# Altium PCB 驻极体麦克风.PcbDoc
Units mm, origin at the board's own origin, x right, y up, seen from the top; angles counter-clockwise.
Board outline 39.6 x 39.6 mm, 2 copper layers (Top Layer, Bottom Layer); 11 components, 10 nets, 34 pads, 3 vias.
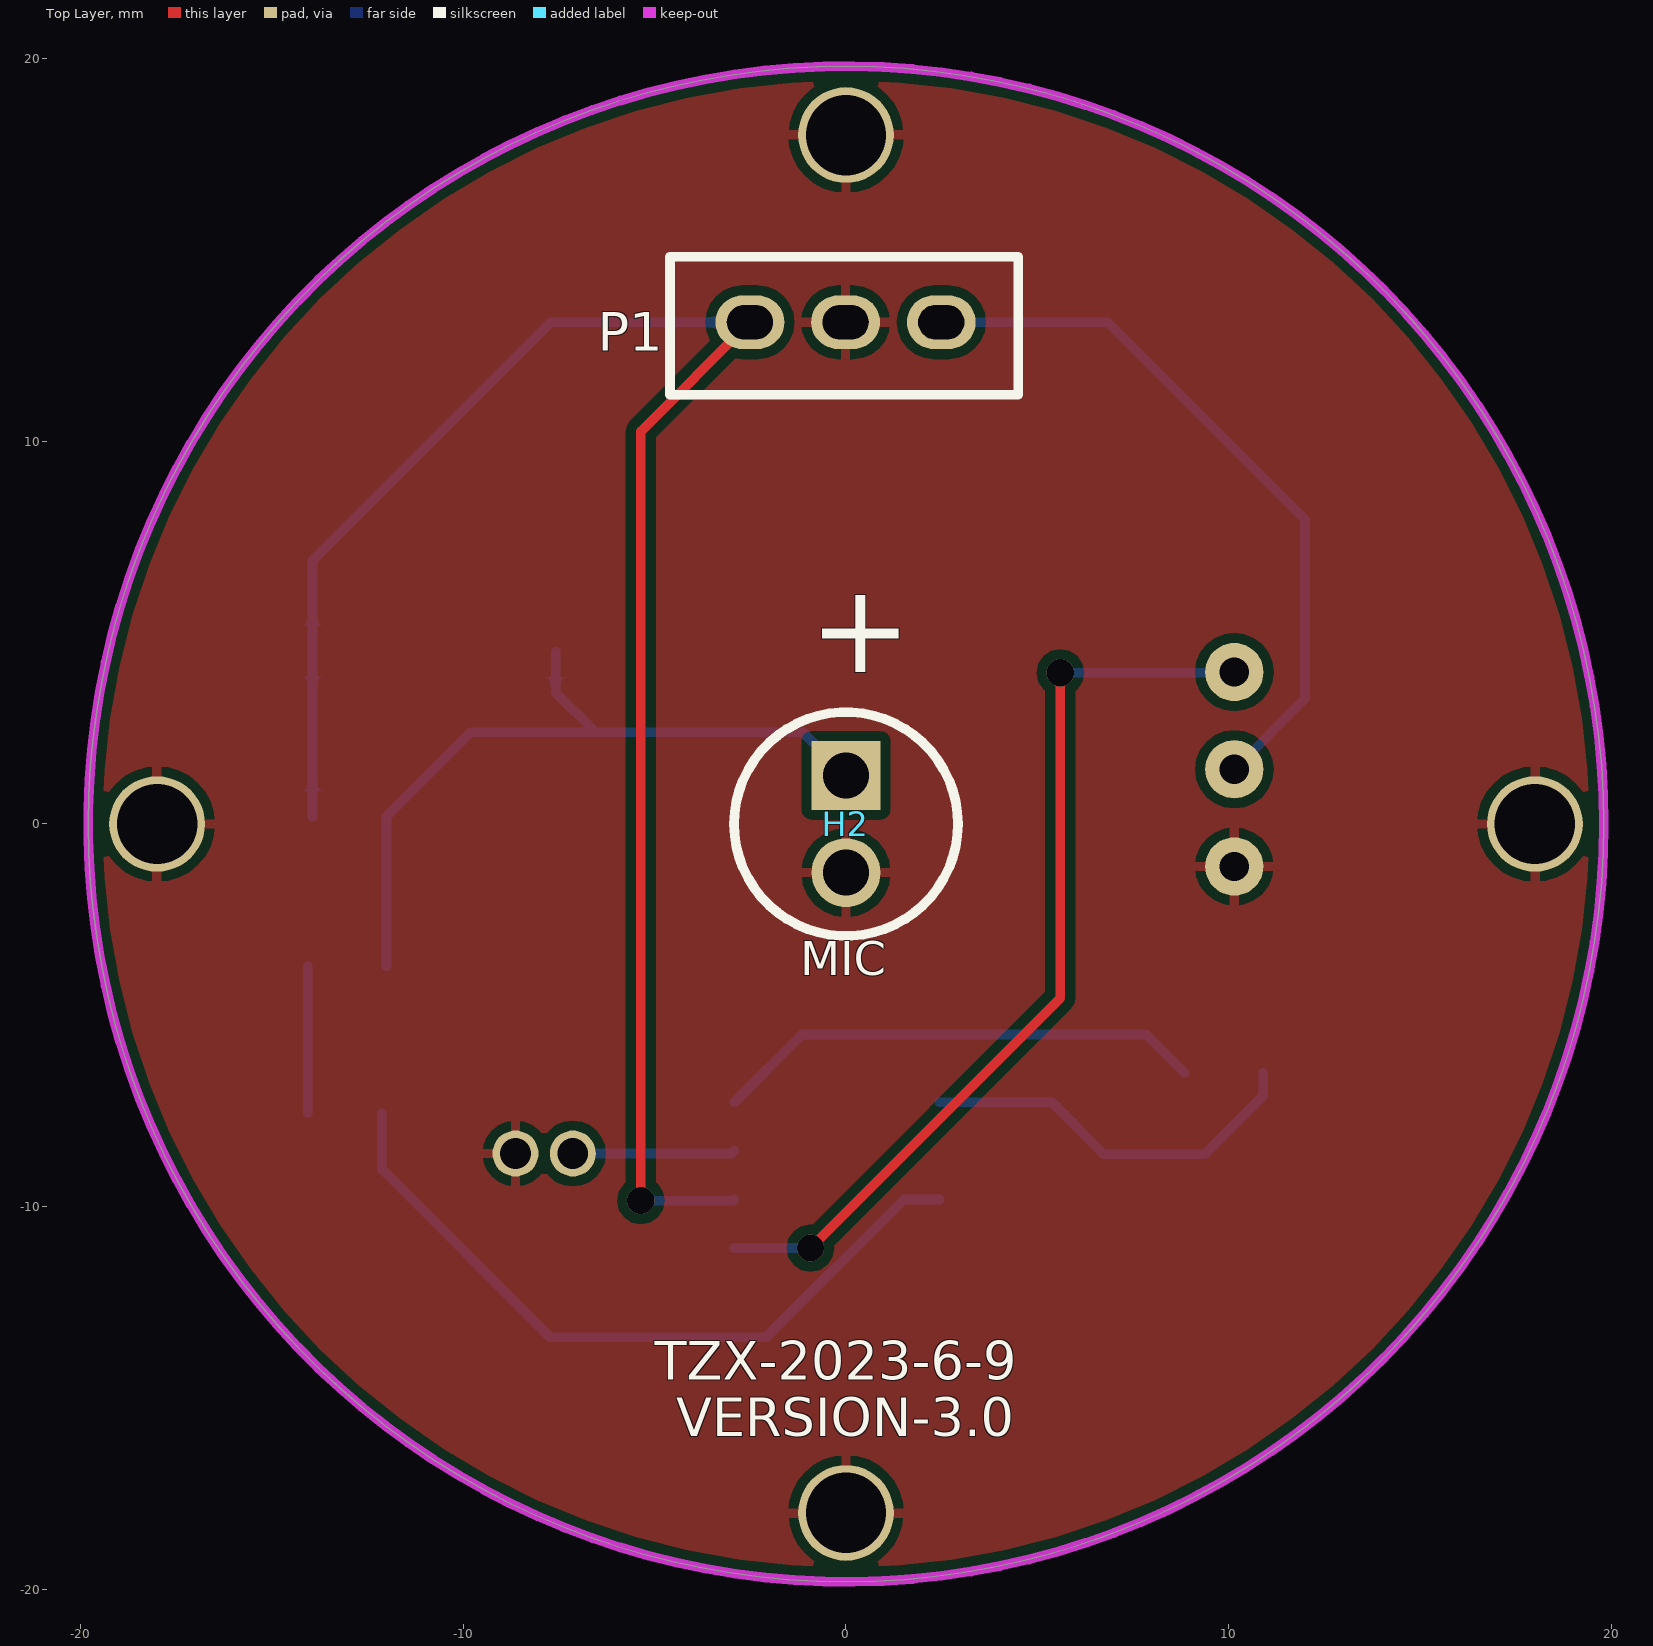
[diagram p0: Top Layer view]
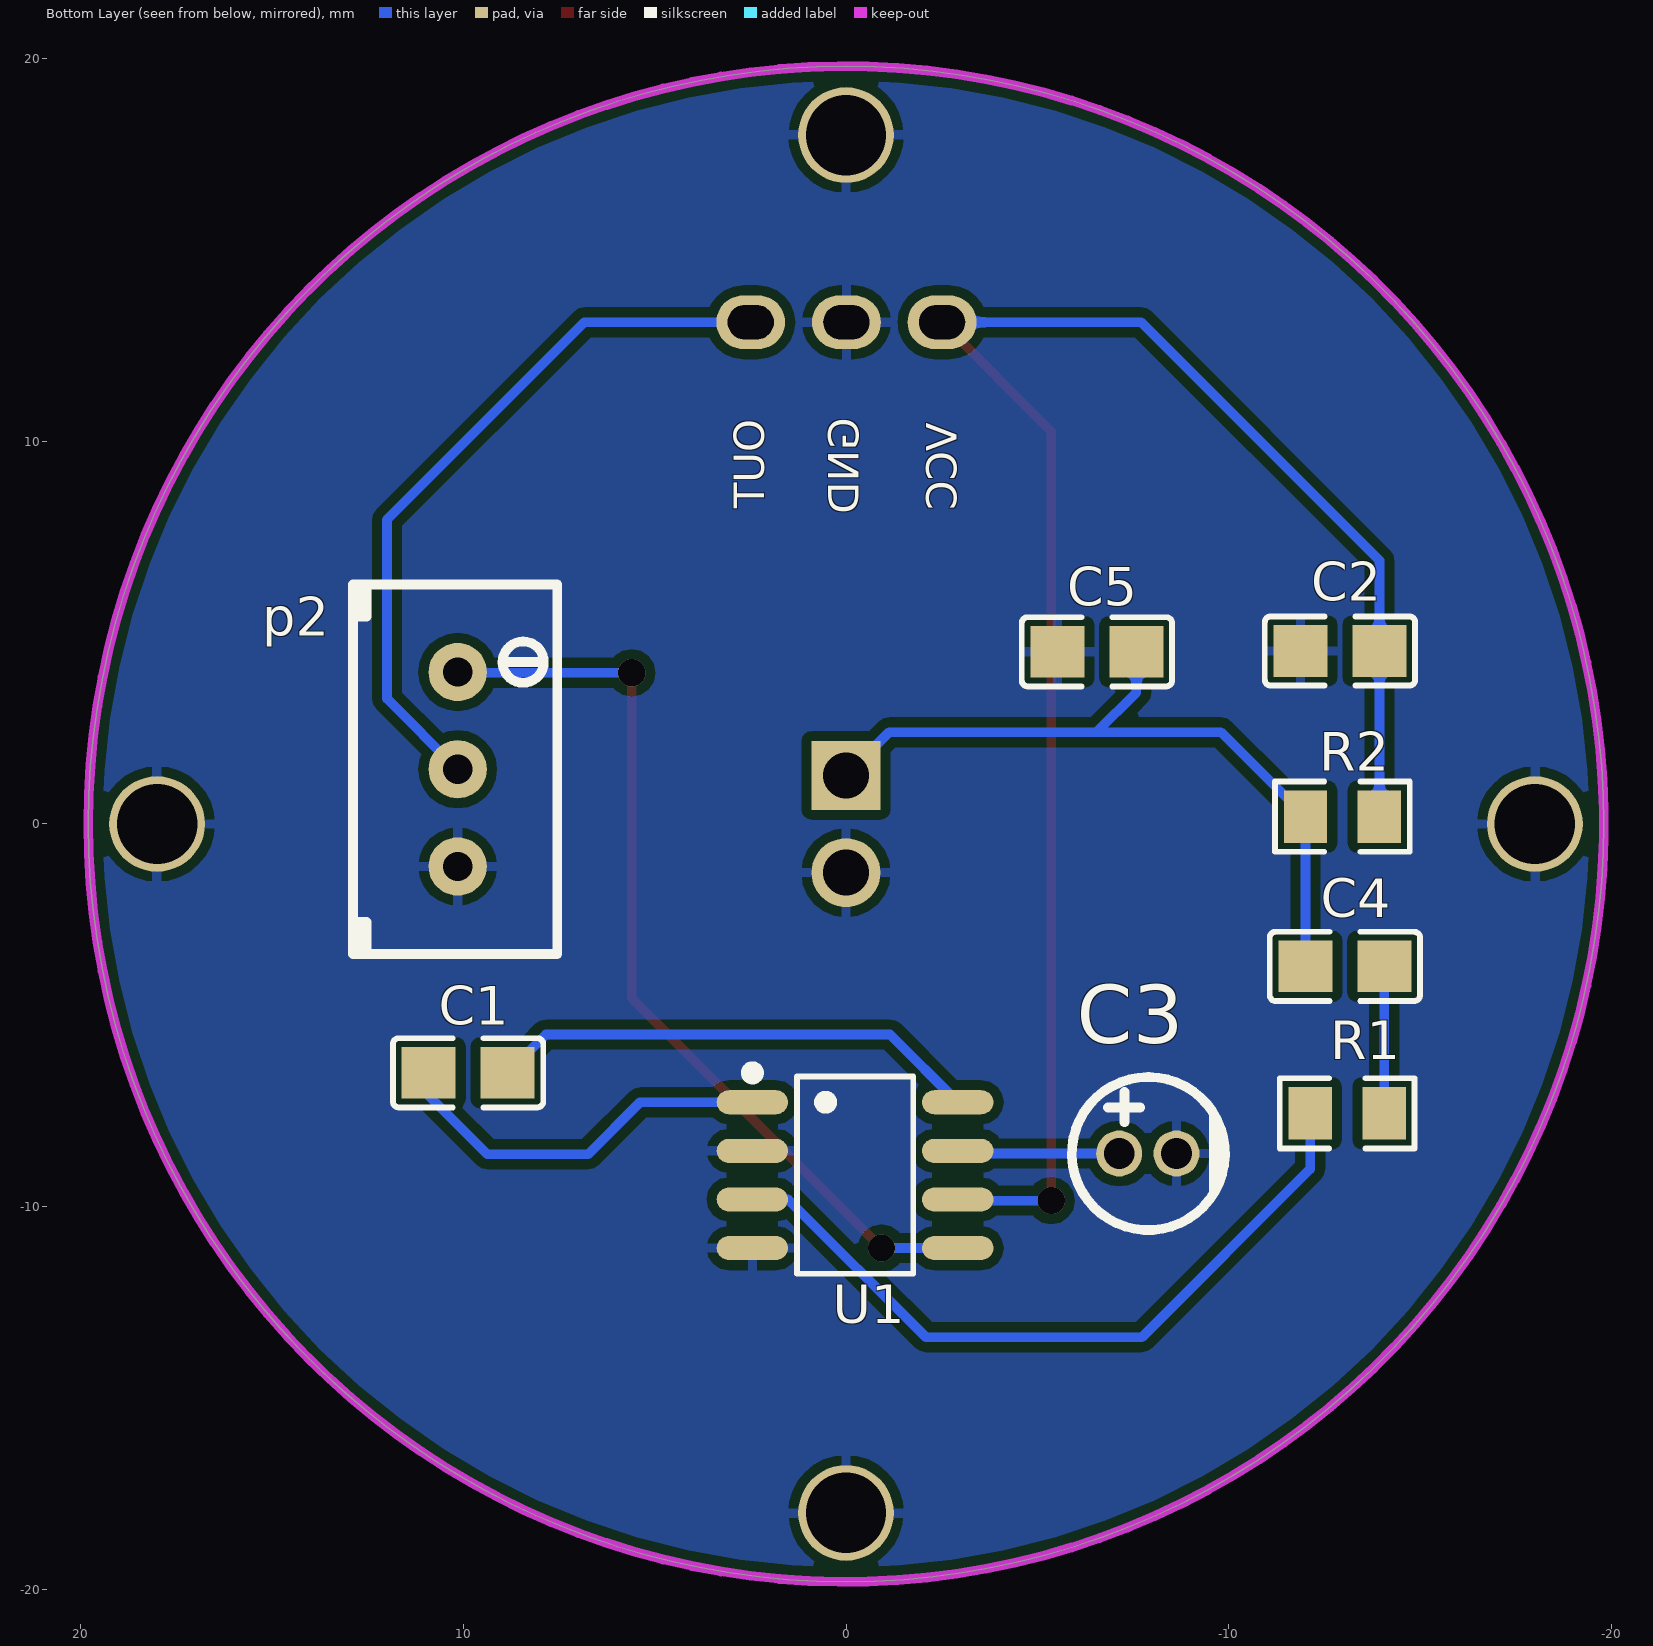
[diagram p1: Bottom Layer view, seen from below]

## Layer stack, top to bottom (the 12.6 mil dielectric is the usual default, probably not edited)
Top Solder: solder mask 0.0102, Solder Resist, Dk 3.5
Top Layer: signal copper 0.0356
Dielectric 1: dielectric 0.32, FR-4, Dk 4.8
Bottom Layer: signal copper 0.0356
Bottom Solder: solder mask 0.0102, Solder Resist, Dk 3.5

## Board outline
-19.8,0 ccw(c0,0) 0,-19.8 ccw(c0,0) 19.8,0 ccw(c0,0) 0,19.8 ccw(c0,0)

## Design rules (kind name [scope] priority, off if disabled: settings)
Clearance [All] p1: gap=0.254 ignorepadtopadclearanceinfootprint=FALSE except(0: Arc-Hole Track-Hole SMDPad-Hole THPad-Hole Via-Hole Fill-Hole Poly-Hole Region-Hole Text-Hole)
PolygonConnect [All] p1: connectstyle=Relief reliefconductorwidth=0.254 reliefentries=4 polygonreliefangle="90 Angle" airgapwidth=0.254
RoutingVias [All] p1: holewidth=0.711 width=1.27 viastyle="Through Hole" minholewidth=0.711 minwidth=1.27 maxholewidth=0.711 maxwidth=1.27
SolderMaskExpansion [All] p1: expansion=0.102
Width [All] p1: maxlimit=0.254 minlimit=0.254 preferedwidth=0.254
30 further rules are at their usual default settings.

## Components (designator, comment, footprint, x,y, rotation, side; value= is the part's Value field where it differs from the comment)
C1 "10uF电容" C0805 10.06,-6.5 r180 bottom
C2 "104电容" C0805 -12.72,4.52 r180 bottom
C3 "10uF电解直插" CAP-TH_BD4.0-P1.50-D0.8-FD -7.91,-8.61 r180 bottom
C4 "106电容" C0805 -12.847,-3.72 r180 bottom
C5 "104电容" C0805 -6.37,4.5 r180 bottom
H2 "MIC" HDR-TH_2P-P2.54-V-M-1 0,0 r270 top
P1 "VC-OUT" VC-OUT 1256.869,-295.774 r0 top
p2 "电位器" 电位器 16.563,3.843 r180 bottom (schematic designator P2)
R1 "330Ω" R0805 -13.382,-7.56 r0 bottom
R2 "10KΩ" R0805 -12.682,0.19 r180 bottom
U1 "LM386D" SOP-8_L4.9-W3.9-P1.27-LS6.0-BL -431.603,413.233 r270 bottom

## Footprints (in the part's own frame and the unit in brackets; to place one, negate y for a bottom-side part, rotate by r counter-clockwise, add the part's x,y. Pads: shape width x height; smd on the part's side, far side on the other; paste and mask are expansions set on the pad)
C0805 [mm]
  rect 1.41x1.35 smd: 1(-0.843,0) 2(1.217,0)
  silkscreen extent -1.78,-0.9 2.15,0.9
CAP-TH_BD4.0-P1.50-D0.8-FD [mm]
  round 1.2 hole 0.8: 1(-0.775,0.001) 2(0.725,0.001)
  silkscreen extent -2.01,-2 2.03,2
HDR-TH_2P-P2.54-V-M-1 [mm]
  rect 1.8x1.8 hole 1.2: 1(-1.27,0)
  round 1.8 hole 1.2: 2(1.27,0)
  silkscreen extent -2.92,-2.92 2.92,2.92
R0805 [mm]
  rect 1.133x1.377 smd: 1(-0.678,0) 2(1.254,0)
  silkscreen extent -1.47,-0.92 2.05,0.92
SOP-8_L4.9-W3.9-P1.27-LS6.0-BL [mm]
  oval 0.63x1.865 smd: 1(420.503,-434.048) 2(421.773,-434.048) 3(423.043,-434.048) 4(424.313,-434.048) 5(424.313,-428.683) 6(423.043,-428.683) 7(421.773,-428.683) 8(420.503,-428.683)
  silkscreen extent 419.59,-434.2 424.98,-429.84
VC-OUT [mm]
  oval 1.8x1.4 hole 0.9 slot 1.2 at 0 deg: 1(-1259.379,308.884) 2(-1256.879,308.884) 3(-1254.379,308.884)
  silkscreen extent -1261.47,306.99 -1252.37,310.59
电位器 [mil]
  round 60 hole 30 paste+0 mask+2: 1(252.64,4.99) 2(252.64,-95.01) 3(252.64,-195.01)
  silkscreen extent 145,-285 355,95

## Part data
C4: library part 104电容
H2: library part 2p

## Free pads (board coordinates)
  round 2.5 hole 2.1: 3(-18,0) 3(0,-18) 3(0,18) 3(18,0)

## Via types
v1: diameter 0.711, hole 0.711, Top Layer to Bottom Layer, 3 vias

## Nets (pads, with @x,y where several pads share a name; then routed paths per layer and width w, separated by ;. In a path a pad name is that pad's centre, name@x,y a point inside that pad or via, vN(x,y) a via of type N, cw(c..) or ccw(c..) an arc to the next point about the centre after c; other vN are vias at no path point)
GND: C2.1 C3.2 C5.1 H2.2 P1.2 p2.3 pad.3 U1.2 U1.4
NetC1_1: C1.1 U1.1 | length 10.3
  Bottom Layer w0.254: U1.1 5.38,-7.27 6.74,-8.63 9.37,-8.63 10.903,-7.097 C1.1
NetC1_2: C1.2 U1.8 | length 12.9
  Bottom Layer w0.254: U1.8 -1.15,-5.5 7.843,-5.5 C1.2
NetC3_1: C3.1 U1.7 | length 4.2
  Bottom Layer w0.254: C3.1 -2.989,-8.609 U1.7
NetC4_1: C4.1 C5.2 H2.1 R2.1 | length 19.8
  Bottom Layer w0.254: C4.1 R2.1 -9.794,2.4 -6.55,2.4 ; C5.2 -7.587,3.437 -6.55,2.4 ; H2.1 -1.13,2.4 -6.55,2.4
NetC4_2: C4.2 R1.1 | length 3.8
  Bottom Layer w0.254: C4.2 -14.064,-7.556 R1.1
NetP1_3: P1.3 p2.2 | length 18.9
  Bottom Layer w0.254: P1.3 6.83,13.11 11.99,7.95 11.99,3.274 p2.2
NetP2_1: p2.1 U1.5 | length 24.4
  Top Layer w0.254: v1(-0.93,-11.08) 5.6,-4.55 v1(5.6,3.95)
  Bottom Layer w0.254: U1.5 v1(-0.93,-11.08) ; v1(5.6,3.95) 10.126,3.95 p2.1 p2.1@9.98,3.97
NetR1_2: R1.2 U1.3 | length 19.3
  Bottom Layer w0.254: R1.2 -12.127,-9.013 -7.73,-13.41 -2.09,-13.41 1.51,-9.81 U1.3
VCC: C2.2 P1.1 R2.2 U1.6 | length 47.3
  Top Layer w0.254: v1(-5.36,-9.84) -5.36,10.26 P1.1
  Bottom Layer w0.254: R2.2 C2.2 -13.937,6.883 -7.71,13.11 P1.1 ; v1(-5.36,-9.84) -2.95,-9.84 U1.6

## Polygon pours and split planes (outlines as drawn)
GND on Top Layer "GND_L01_P004" (solid, remove dead copper, pour order 4): -19.8,0 ccw(c0,0) 0,-19.8 ccw(c0,0) 19.8,0 ccw(c0,0) 0,19.8 ccw(c0,0)
GND on Bottom Layer "GND_L02_P005" (solid, remove dead copper, pour order 5): -19.8,0 ccw(c0,0) 0,-19.8 ccw(c0,0) 19.8,0 ccw(c0,0) 0,19.8 ccw(c0,0)

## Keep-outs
Keep-Out Layer:
  circle w0.254: c0,0 r19.8

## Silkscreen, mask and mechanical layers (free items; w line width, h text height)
Top Overlay:
  text "+" at -0.96,3.2 h4
  text "TZX-2023-6-9" at -5,-14.52 h1
  text "VERSION-3.0" at -4.43,-16 h1
Bottom Overlay:
  text "GND" at -0.33,10.62 h0.8 r270
  text "OUT" at 2.14,10.58 h0.8 r270
  text "VCC" at -2.89,10.49 h0.8 r270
